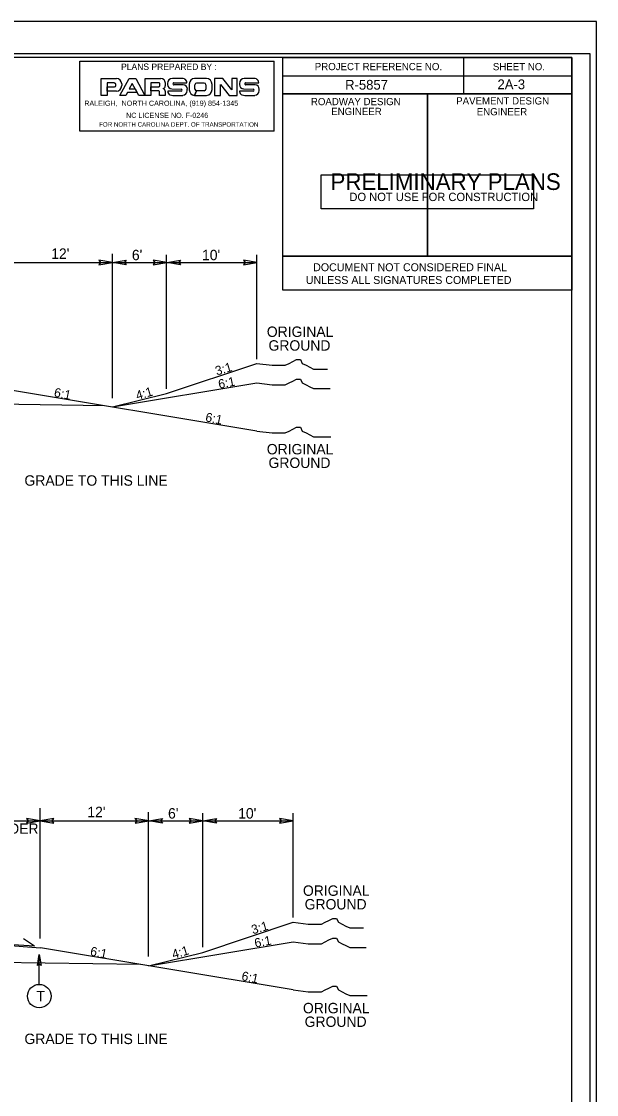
# Model space of a CAD drawing. Extents: x 2176156 to 2177167, y 76401 to 76644.
# Drawn here: x 2176835.1 to 2176898.7, y 76511.6 to 76630.5 of the extents above; entities that cross this region are included whole.
import ezdxf

# ---------------------------------------------------------------- set-up
doc = ezdxf.new("R2010")
doc.units = 0
for name, color, linetype in [('Exist Building', 7, 'Continuous'), ('Exist Roads Curbs', 7, 'Continuous'), ('Exist Roads EOP Other', 7, 'Continuous'), ('Exist Roads Soil', 7, 'Continuous'), ('Exist Structure Minor Catch Basin', 7, 'Continuous'), ('Exist Structure Minor Culvert Topo', 7, 'Continuous'), ('Exist Utilities Other Pole CELL', 7, 'Continuous'), ('Old_Level_1', 7, 'Continuous'), ('Old_Level_2', 7, 'Continuous'), ('Old_Level_3', 7, 'Continuous'), ('PH Exist DTM Breakline', 7, 'Continuous'), ('Prop North Arrow NAD83 for Plan Sheets CELL', 7, 'Continuous'), ('Sheet Cutting Line CELL', 7, 'Continuous'), ('Sheet Data Field CELL', 7, 'Continuous'), ('Sheet Plot Border Inside CELL', 7, 'Continuous'), ('Sheet Plot Border Outside CELL', 7, 'Continuous'), ('Sheet Sticker Exception Certification CELL', 7, 'Continuous')]:
    doc.layers.add(name, color=color, linetype=linetype)

msp = doc.modelspace()

# ---------------------------------------------------------------- linework, layer by layer
at = {"layer": 'Exist Building'}
for p, q in [((2176844.25, 76587.91), (2176804.07, 76588.51)), ((2176848.25, 76526.01), (2176804.07, 76526.66))]:
    msp.add_line(p, q, dxfattribs=at)
at = {"layer": 'Exist Roads Curbs'}
for points in [[(2176861.13, 76592.6), (2176862.8, 76592.39), (2176863.22, 76592.39), (2176863.85, 76592.39), (2176864.27, 76592.39), (2176864.68, 76592.6), (2176865.1, 76592.81), (2176865.52, 76593.02), (2176865.94, 76593.02), (2176866.15, 76592.6), (2176866.56, 76592.39), (2176866.98, 76592.18), (2176867.4, 76591.97), (2176867.82, 76591.97), (2176868.23, 76591.97), (2176868.65, 76591.97), (2176868.92, 76591.97)], [(2176861.13, 76590.43), (2176862.8, 76590.22), (2176863.22, 76590.22), (2176863.85, 76590.22), (2176864.27, 76590.22), (2176864.68, 76590.43), (2176865.1, 76590.64), (2176865.52, 76590.85), (2176865.94, 76590.85), (2176866.15, 76590.43), (2176866.56, 76590.22), (2176866.98, 76590.02), (2176867.4, 76589.81), (2176867.82, 76589.81), (2176868.24, 76589.81), (2176868.65, 76589.81), (2176869.07, 76589.81), (2176869.23, 76589.81)], [(2176861.13, 76585.1), (2176862.8, 76584.89), (2176863.22, 76584.89), (2176863.85, 76584.89), (2176864.27, 76584.89), (2176864.68, 76585.1), (2176865.1, 76585.31), (2176865.52, 76585.52), (2176865.94, 76585.52), (2176866.15, 76585.1), (2176866.56, 76584.89), (2176866.98, 76584.68), (2176867.4, 76584.47), (2176867.82, 76584.47), (2176868.23, 76584.47), (2176868.65, 76584.47), (2176869.07, 76584.47), (2176869.31, 76584.47)], [(2176865.13, 76530.69), (2176866.8, 76530.48), (2176867.22, 76530.48), (2176867.85, 76530.48), (2176868.27, 76530.48), (2176868.68, 76530.69), (2176869.1, 76530.9), (2176869.52, 76531.11), (2176869.94, 76531.11), (2176870.15, 76530.69), (2176870.56, 76530.48), (2176870.98, 76530.27), (2176871.4, 76530.07), (2176871.82, 76530.07), (2176872.23, 76530.07), (2176872.65, 76530.07), (2176872.92, 76530.07)], [(2176865.13, 76528.53), (2176866.8, 76528.32), (2176867.22, 76528.32), (2176867.85, 76528.32), (2176868.27, 76528.32), (2176868.68, 76528.53), (2176869.1, 76528.74), (2176869.52, 76528.94), (2176869.94, 76528.94), (2176870.15, 76528.53), (2176870.56, 76528.32), (2176870.98, 76528.11), (2176871.4, 76527.9), (2176871.82, 76527.9), (2176872.24, 76527.9), (2176872.65, 76527.9), (2176873.07, 76527.9), (2176873.23, 76527.9)], [(2176865.13, 76523.19), (2176866.8, 76522.98), (2176867.22, 76522.98), (2176867.85, 76522.98), (2176868.27, 76522.98), (2176868.68, 76523.19), (2176869.1, 76523.4), (2176869.52, 76523.61), (2176869.94, 76523.61), (2176870.15, 76523.19), (2176870.56, 76522.98), (2176870.98, 76522.77), (2176871.4, 76522.57), (2176871.82, 76522.57), (2176872.23, 76522.57), (2176872.65, 76522.57), (2176873.07, 76522.57), (2176873.31, 76522.57)]]:
    msp.add_lwpolyline(points, dxfattribs=at)
at = {"layer": 'Exist Roads EOP Other'}
for p, q in [((2176851.13, 76589.27), (2176861.13, 76592.6)), ((2176845.13, 76587.77), (2176851.13, 76589.27)), ((2176855.13, 76527.36), (2176865.13, 76530.69)), ((2176831.15, 76528.33), (2176837.18, 76527.85)), ((2176849.13, 76525.86), (2176855.13, 76527.36))]:
    msp.add_line(p, q, dxfattribs=at)
at = {"layer": 'Exist Roads Soil'}
for p, q in [((2176845.13, 76587.77), (2176861.13, 76590.43)), ((2176861.13, 76585.1), (2176833.18, 76589.76)), ((2176849.13, 76525.86), (2176865.13, 76528.53)), ((2176865.13, 76523.19), (2176837.18, 76527.85))]:
    msp.add_line(p, q, dxfattribs=at)
at = {"layer": 'Exist Structure Minor Catch Basin'}
msp.add_lwpolyline([(2176868.23, 76609.71), (2176868.23, 76613.47), (2176891.75, 76613.47), (2176891.75, 76609.71)], close=True, dxfattribs=at)
at = {"layer": 'Exist Utilities Other Pole CELL'}
for q in [(2176835.29, 76528.86), (2176831.77, 76528.36)]:
    msp.add_line((2176836.52, 76528.04), q, dxfattribs=at)
at = {"layer": 'Old_Level_1'}
for points in [[(2176843.64, 76603.52), (2176845.15, 76603.78), (2176843.63, 76604.05), (2176843.82, 76603.78)], [(2176846.66, 76603.52), (2176845.15, 76603.78), (2176846.66, 76604.05), (2176846.47, 76603.78)], [(2176849.64, 76603.52), (2176851.15, 76603.78), (2176849.63, 76604.05), (2176849.82, 76603.78)], [(2176852.66, 76603.52), (2176851.15, 76603.78), (2176852.66, 76604.05), (2176852.47, 76603.78)], [(2176859.64, 76603.52), (2176861.15, 76603.78), (2176859.63, 76604.05), (2176859.82, 76603.78)], [(2176835.64, 76541.67), (2176837.15, 76541.93), (2176835.63, 76542.2), (2176835.82, 76541.93)], [(2176838.66, 76542.19), (2176837.15, 76541.93), (2176838.66, 76541.66), (2176838.47, 76541.93)], [(2176847.64, 76541.67), (2176849.15, 76541.93), (2176847.63, 76542.2), (2176847.82, 76541.93)], [(2176850.66, 76541.67), (2176849.15, 76541.93), (2176850.66, 76542.2), (2176850.47, 76541.93)], [(2176853.64, 76541.67), (2176855.15, 76541.93), (2176853.63, 76542.2), (2176853.82, 76541.93)], [(2176856.66, 76541.67), (2176855.15, 76541.93), (2176856.66, 76542.2), (2176856.47, 76541.93)], [(2176863.64, 76541.67), (2176865.15, 76541.93), (2176863.63, 76542.2), (2176863.82, 76541.93)]]:
    msp.add_lwpolyline(points, close=True, dxfattribs=at)
at = {"layer": 'Old_Level_2'}
for p, q in [((2176863.98, 76600.71), (2176863.98, 76604.47)), ((2176863.98, 76604.47), (2176895.99, 76604.47)), ((2176895.99, 76604.47), (2176895.99, 76600.71)), ((2176895.99, 76600.71), (2176863.98, 76600.71))]:
    msp.add_line(p, q, dxfattribs=at)
at = {"layer": 'Old_Level_3'}
for p, q in [((2176845.13, 76588.75), (2176845.13, 76604.75)), ((2176851.13, 76589.77), (2176851.13, 76604.61)), ((2176861.13, 76593.07), (2176861.13, 76604.61)), ((2176797.15, 76603.78), (2176861.13, 76603.78)), ((2176837.15, 76528.9), (2176837.15, 76543.33)), ((2176849.13, 76526.9), (2176849.13, 76542.9)), ((2176855.13, 76527.92), (2176855.13, 76542.76)), ((2176865.13, 76531.22), (2176865.13, 76542.76)), ((2176797.17, 76541.93), (2176865.13, 76541.93))]:
    msp.add_line(p, q, dxfattribs=at)
at = {"layer": 'PH Exist DTM Breakline'}
for p, q in [((2176841.54, 76626.09), (2176863.04, 76626.09)), ((2176841.54, 76618.34), (2176841.54, 76626.09)), ((2176863.04, 76618.34), (2176863.04, 76626.09)), ((2176850.39, 76623.37), (2176850.39, 76623.58)), ((2176850.99, 76623.64), (2176850.99, 76623.35)), ((2176851.23, 76623.59), (2176851.23, 76623.51)), ((2176852.83, 76624.16), (2176851.77, 76624.16)), ((2176851.94, 76623.69), (2176853.38, 76623.69)), ((2176855.53, 76624.16), (2176854.23, 76624.16)), ((2176854.45, 76623.66), (2176855.3, 76623.66)), ((2176859.19, 76623.59), (2176859.19, 76623.51)), ((2176860.79, 76624.16), (2176859.73, 76624.16)), ((2176859.9, 76623.69), (2176861.34, 76623.69)), ((2176845.51, 76623.4), (2176845.51, 76623.51)), ((2176846.16, 76623.55), (2176846.16, 76623.37)), ((2176851.7, 76623), (2176852.75, 76622.98)), ((2176852.97, 76623.45), (2176851.94, 76623.45)), ((2176853.42, 76622.82), (2176853.42, 76622.96)), ((2176853.64, 76623.53), (2176853.64, 76622.9)), ((2176854.21, 76622.29), (2176854.45, 76622.79)), ((2176854.27, 76622.99), (2176854.27, 76623.47)), ((2176855.48, 76623.46), (2176855.48, 76622.99)), ((2176856.16, 76622.95), (2176856.16, 76623.48)), ((2176859.66, 76623), (2176860.71, 76622.98)), ((2176860.93, 76623.45), (2176859.9, 76623.45)), ((2176861.38, 76622.82), (2176861.38, 76622.96)), ((2176851.83, 76622.29), (2176852.93, 76622.29)), ((2176854.21, 76622.29), (2176855.55, 76622.29)), ((2176859.8, 76622.29), (2176860.89, 76622.29)), ((2176863.04, 76618.34), (2176841.54, 76618.34))]:
    msp.add_line(p, q, dxfattribs=at)
for points in [[(2176845.37, 76623.66), (2176844.54, 76623.66), (2176844.54, 76623.23), (2176844.55, 76622.75), (2176844.55, 76622.29), (2176843.89, 76622.29), (2176843.89, 76624.16), (2176845.59, 76624.16)], [(2176850.31, 76623.66), (2176849.38, 76623.66), (2176849.38, 76623.24), (2176849.38, 76622.79), (2176849.38, 76622.29), (2176848.76, 76622.29), (2176848.76, 76624.16), (2176850.5, 76624.16)], [(2176845.59, 76622.75), (2176844.55, 76622.75), (2176844.54, 76623.23), (2176845.35, 76623.23)], [(2176850.99, 76622.69), (2176850.99, 76622.29), (2176850.36, 76622.29), (2176850.36, 76622.72), (2176850.28, 76622.79), (2176849.38, 76622.79), (2176849.38, 76623.24), (2176850.27, 76623.24)], [(2176852.75, 76622.74), (2176851.25, 76622.74), (2176851.25, 76622.71)], [(2176855.3, 76622.79), (2176854.45, 76622.79), (2176854.21, 76622.29), (2176855.55, 76622.29)], [(2176860.71, 76622.74), (2176859.21, 76622.74), (2176859.21, 76622.71)]]:
    msp.add_lwpolyline(points, dxfattribs=at)
for points in [[(2176845.94, 76622.29), (2176846.98, 76624.16), (2176847.72, 76624.16), (2176848.74, 76622.29), (2176848.04, 76622.29), (2176847.33, 76623.6), (2176847, 76623), (2176847.65, 76623), (2176847.87, 76622.61), (2176846.79, 76622.61), (2176846.62, 76622.29)], [(2176856.45, 76624.16), (2176856.45, 76622.29), (2176857.08, 76622.29), (2176857.08, 76623.5), (2176858.06, 76622.29), (2176858.95, 76622.29), (2176858.95, 76624.16), (2176858.34, 76624.16), (2176858.34, 76622.91), (2176857.36, 76624.16)]]:
    msp.add_lwpolyline(points, close=True, dxfattribs=at)
for centre, major_axis, ratio, start_param, end_param in [((2176845.37, 76623.51), (0, 0.147), 0.93676, 4.712389, 6.283185), ((2176845.59, 76623.55), (0, 0.612), 0.93676, 4.712389, 6.283185), ((2176850.31, 76623.57), (0, 0.0857), 0.934072, 4.712389, 6.283185), ((2176850.5, 76623.64), (0, 0.526), 0.934072, 4.712389, 6.283185), ((2176851.77, 76623.59), (0, 0.575), 0.934072, 0, 1.570796), ((2176851.94, 76623.57), (0, 0.116), 0.934072, 0, 3.141593), ((2176852.83, 76623.37), (0, 0.796), 0.934072, 5.902203, 6.283185), ((2176852.94, 76623.67), (0, 0.465), 0.934072, 4.738699, 5.901866), ((2176854.23, 76623.53), (0, 0.637), 0.924824, 0, 1.570796), ((2176854.45, 76623.46), (0, -0.196), 0.924824, 3.141593, 4.712389), ((2176855.3, 76623.46), (0, 0.196), 0.924824, 4.712389, 6.283185), ((2176855.53, 76623.48), (0, 0.686), 0.924824, 4.712389, 6.283185), ((2176859.73, 76623.59), (0, 0.575), 0.934072, 0, 1.570796), ((2176859.9, 76623.57), (0, 0.116), 0.934072, 0, 3.141593), ((2176860.79, 76623.37), (0, 0.796), 0.934072, 5.902203, 6.283185), ((2176860.9, 76623.67), (0, 0.465), 0.934072, 4.738699, 5.901866), ((2176845.35, 76623.4), (0, 0.171), 0.93676, 3.141593, 4.712389), ((2176845.59, 76623.37), (0, 0.612), 0.93676, 3.141593, 4.712389), ((2176850.27, 76623.37), (0, 0.122), 0.934072, 3.141593, 4.712389), ((2176850.69, 76623.35), (0, 0.318), 0.934072, 3.34512, 4.712389), ((2176850.65, 76622.69), (0, 0.367), 0.934072, 4.712389, 5.969561), ((2176851.71, 76623.51), (0, -0.514), 0.934072, 4.712389, 6.260753), ((2176851.61, 76622.71), (0, -0.379), 0.934072, 4.712389, 5.988639), ((2176852.75, 76622.86), (0, 0.116), 0.934072, 3.141593, 6.283185), ((2176852.93, 76622.82), (0, 0.526), 0.934072, 3.141593, 4.712389), ((2176852.97, 76622.96), (0, 0.49), 0.934072, 4.712389, 6.283185), ((2176854.21, 76622.9), (0, -0.612), 0.924824, 4.712389, 6.283185), ((2176854.45, 76622.99), (0, -0.196), 0.924824, 4.712389, 6.283185), ((2176855.3, 76622.99), (0, 0.196), 0.924824, 3.141593, 4.712389), ((2176855.55, 76622.95), (0, 0.661), 0.924824, 3.141593, 4.712389), ((2176859.67, 76623.51), (0, -0.514), 0.934072, 4.712389, 6.260753), ((2176859.57, 76622.71), (0, -0.379), 0.934072, 4.712389, 5.988639), ((2176860.71, 76622.86), (0, 0.116), 0.934072, 3.141593, 6.283185), ((2176860.89, 76622.82), (0, 0.526), 0.934072, 3.141593, 4.712389), ((2176860.93, 76622.96), (0, 0.49), 0.934072, 4.712389, 6.283185), ((2176851.83, 76623.51), (0, 1.22), 0.934072, 2.847261, 3.141593), ((2176859.8, 76623.51), (0, 1.22), 0.934072, 2.847261, 3.141593)]:
    msp.add_ellipse(centre, major_axis=major_axis, ratio=ratio, start_param=start_param, end_param=end_param, dxfattribs=at)
at = {"layer": 'Prop North Arrow NAD83 for Plan Sheets CELL'}
msp.add_line((2176837.04, 76523.81), (2176837.04, 76527.11), dxfattribs=at)
msp.add_lwpolyline([(2176836.83, 76525.91), (2176837.04, 76527.11), (2176837.25, 76525.9), (2176837.04, 76526.05)], close=True, dxfattribs=at)
msp.add_circle((2176837.04, 76522.51), 1.3, dxfattribs=at)
at = {"layer": 'Sheet Cutting Line CELL'}
msp.add_lwpolyline([(2176898.71, 76630.48), (2176629.27, 76630.48), (2176629.27, 76454.48), (2176898.71, 76454.48)], close=True, dxfattribs=at)
at = {"layer": 'Sheet Data Field CELL'}
for p, q in [((2176883.99, 76626.47), (2176883.99, 76622.47)), ((2176863.98, 76624.47), (2176895.99, 76624.47)), ((2176879.99, 76622.47), (2176879.99, 76604.48))]:
    msp.add_line(p, q, dxfattribs=at)
for points in [[(2176895.99, 76626.48), (2176655.99, 76626.48), (2176655.99, 76458.48), (2176895.99, 76458.48)], [(2176863.98, 76626.48), (2176895.99, 76626.48), (2176895.99, 76622.47), (2176863.98, 76622.47)], [(2176863.98, 76622.47), (2176879.99, 76622.47), (2176879.99, 76604.47), (2176863.98, 76604.47)], [(2176879.99, 76622.47), (2176895.99, 76622.47), (2176895.99, 76604.47), (2176879.99, 76604.47)]]:
    msp.add_lwpolyline(points, close=True, dxfattribs=at)
at = {"layer": 'Sheet Plot Border Outside CELL'}
msp.add_lwpolyline([(2176897.99, 76626.88), (2176631.35, 76626.88), (2176631.35, 76458.07), (2176897.99, 76458.07)], close=True, dxfattribs=at)
at = {"layer": 'Sheet Sticker Exception Certification CELL'}
msp.add_line((2176898.71, 76630.48), (2176629.27, 76630.48), dxfattribs=at)

# ---------------------------------------------------------------- texts
at = {"layer": 'Exist Roads Curbs'}
for s, rotation, p in [('3:1', 16.4649, (2176856.68, 76591.25)), ('6:1', 10.8168, (2176856.95, 76589.79)), ('6:1', 348.5135, (2176838.61, 76588.93)), ('4:1', 16.4649, (2176847.89, 76588.53)), ('6:1', 348.5135, (2176855.36, 76586.19)), ('3:1', 16.4649, (2176860.68, 76529.35)), ('6:1', 10.8168, (2176860.95, 76527.88)), ('6:1', 348.5135, (2176842.61, 76527.03)), ('4:1', 16.4649, (2176851.89, 76526.63)), ('6:1', 348.5135, (2176859.36, 76524.29))]:
    msp.add_text(s, height=1.006, rotation=rotation, dxfattribs=at).set_placement(p)
at = {"layer": 'Exist Structure Minor Catch Basin'}
for s, height, p in [('PRELIMINARY PLANS', 1.8432, (2176869.27, 76611.81)), ('DO NOT USE FOR CONSTRUCTION', 0.9216, (2176871.36, 76610.58))]:
    msp.add_text(s, height=height, dxfattribs=at).set_placement(p)
at = {"layer": 'Exist Structure Minor Culvert Topo'}
for s, height, p in [("12' ", 1.153, (2176838.36, 76604.18)), ("6'", 1.153, (2176847.29, 76604.03)), ("10'", 1.153, (2176855.05, 76604.03)), ('ORIGINAL', 1.153, (2176862.22, 76595.53)), ('GROUND', 1.153, (2176862.41, 76594.01)), ('ORIGINAL', 1.153, (2176862.22, 76582.52)), ('GROUND', 1.153, (2176862.41, 76581.01)), ('GRADE TO THIS LINE', 1.1533, (2176835.4, 76579.05)), ("12' ", 1.153, (2176842.36, 76542.33)), ("6'", 1.153, (2176851.29, 76542.18)), ("10'", 1.153, (2176859.05, 76542.18)), ('SHOULDER', 1.153, (2176828.39, 76540.49)), ('ORIGINAL', 1.153, (2176866.22, 76533.62)), ('GROUND', 1.153, (2176866.41, 76532.11)), ('ORIGINAL', 1.153, (2176866.22, 76520.61)), ('GROUND', 1.153, (2176866.41, 76519.1)), ('GRADE TO THIS LINE', 1.1533, (2176835.4, 76517.2))]:
    msp.add_text(s, height=height, dxfattribs=at).set_placement(p)
at = {"layer": 'Old_Level_2'}
for s, p in [('DOCUMENT NOT CONSIDERED FINAL', (2176867.35, 76602.81)), ('UNLESS ALL SIGNATURES COMPLETED', (2176866.54, 76601.4))]:
    msp.add_text(s, height=0.88, dxfattribs=at).set_placement(p)
at = {"layer": 'PH Exist DTM Breakline'}
for s, height, rotation, p in [('PLANS PREPARED BY : ', 0.7063, 359.999, (2176846.09, 76625.11)), ('RALEIGH,  NORTH CAROLINA, (919) 854-1345', 0.5721, 360, (2176842.02, 76621.13)), ('NC LICENSE NO. F-0246', 0.5721, 360, (2176846.65, 76619.79)), ('FOR NORTH CAROLINA DEPT. OF TRANSPORTATION', 0.4962, 359.9999, (2176843.66, 76618.82))]:
    msp.add_text(s, height=height, rotation=rotation, dxfattribs=at).set_placement(p)
at = {"layer": 'Prop North Arrow NAD83 for Plan Sheets CELL'}
msp.add_text('T', height=1.16, rotation=0.0003, dxfattribs=at).set_placement((2176836.71, 76521.93))
at = {"layer": 'Sheet Data Field CELL'}
for s, p in [('PROJECT REFERENCE NO.', (2176867.53, 76625.08)), ('SHEET NO.', (2176887.24, 76625.07)), ('ROADWAY DESIGN', (2176867.1, 76621.2)), ('PAVEMENT DESIGN', (2176883.18, 76621.28)), ('ENGINEER', (2176869.35, 76620.11)), ('ENGINEER', (2176885.45, 76620.08))]:
    msp.add_text(s, height=0.8, dxfattribs=at).set_placement(p)
at = {"layer": 'Sheet Plot Border Inside CELL'}
for s, p in [('R-5857', (2176870.89, 76622.92)), ('2A-3', (2176887.75, 76622.97))]:
    msp.add_text(s, height=1.08, dxfattribs=at).set_placement(p)

doc.saveas('drawing.dxf')
